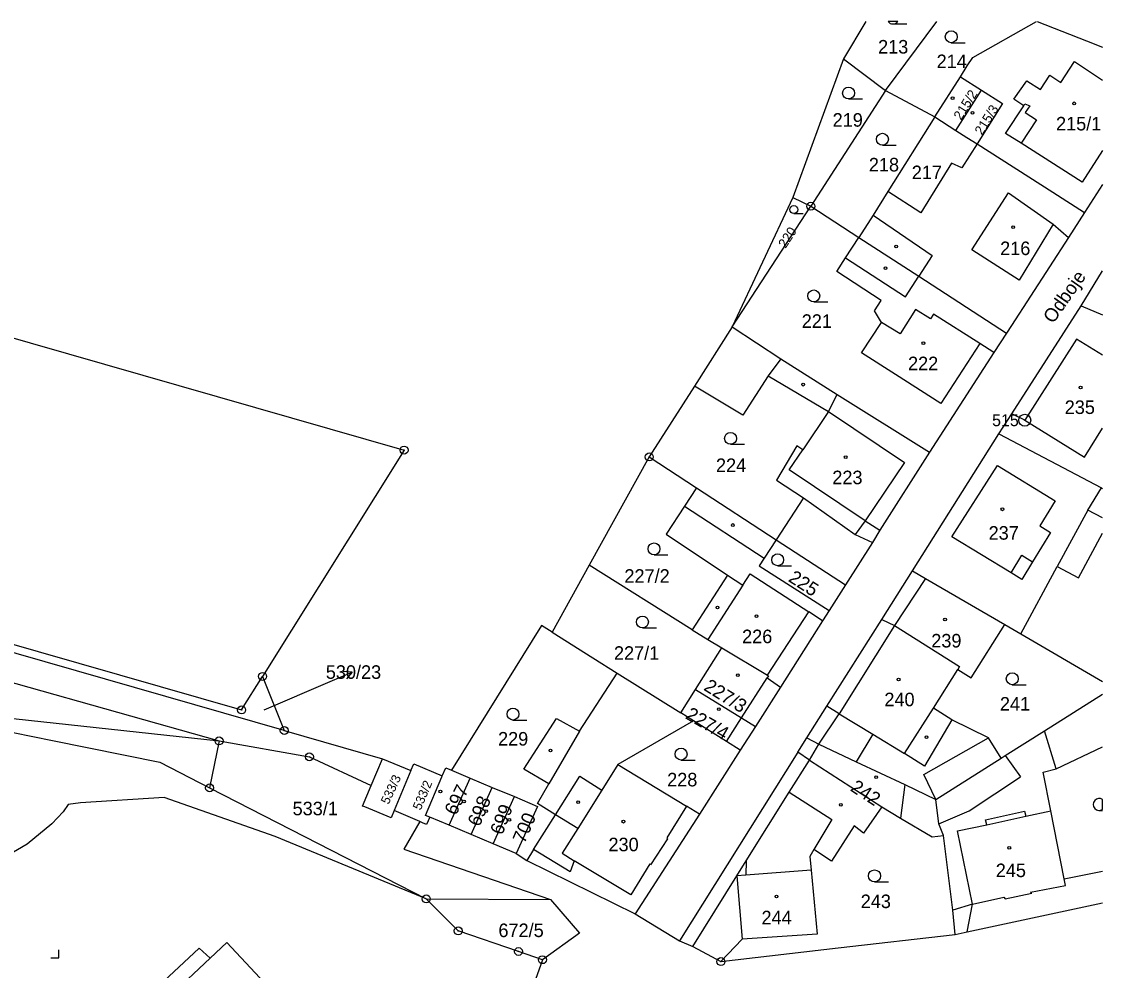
# Model space of a CAD drawing. Extents: x -749778 to -749372, y -967291 to -966955.
# Drawn here: x -749507.7 to -749371.9, y -967074.2 to -966955.1 of the extents above; entities that cross this region are included whole.
import ezdxf

# ---------------------------------------------------------------- set-up
doc = ezdxf.new("R2010")
doc.units = 0
for name, color, linetype in [('Hranice parcel', 7, 'Continuous'), ('Parcelní čísla', 7, 'Continuous'), ('Pop  PČ popisy', 7, 'Continuous'), ('Vnitřní kresba', 7, 'Continuous'), ('Značky bodu BP', 7, 'Continuous'), ('Značky budov', 7, 'Continuous'), ('Značky kultur', 7, 'Continuous')]:
    doc.layers.add(name, color=color, linetype=linetype)

msp = doc.modelspace()

# ---------------------------------------------------------------- linework, layer by layer
at = {"layer": 'Hranice parcel'}
for p, q in [((-749401.64, -966955.06), (-749404.45, -966959.75)), ((-749399.15, -966963.7), (-749392.71, -966955.06)), ((-749404.45, -966959.75), (-749410.8, -966977.16)), ((-749404.45, -966959.75), (-749399.15, -966963.7)), ((-749392.98, -966967.04), (-749389.74, -966962)), ((-749389.74, -966962), (-749387.12, -966963.67)), ((-749399.15, -966963.7), (-749408.54, -966978.26)), ((-749399.15, -966963.7), (-749392.98, -966967.04)), ((-749390.32, -966968.74), (-749387.12, -966963.67)), ((-749392.98, -966967.04), (-749398.86, -966976.41)), ((-749392.98, -966967.04), (-749390.32, -966968.74)), ((-749410.8, -966977.16), (-749418.41, -966993.42)), ((-749418.41, -966993.42), (-749408.54, -966978.26)), ((-749410.8, -966977.16), (-749408.54, -966978.26)), ((-749408.54, -966978.26), (-749402.52, -966982.17)), ((-749374.61, -966990.75), (-749371.93, -966986.38)), ((-749383.32, -967004.33), (-749374.61, -966990.75)), ((-749374.61, -966990.75), (-749371.93, -966991.91)), ((-749418.41, -966993.42), (-749412.33, -966997.43)), ((-749383.99, -966994.19), (-749385.55, -966996.62)), ((-749385.55, -966996.62), (-749393.64, -967009.16)), ((-749384.94, -967006.84), (-749383.32, -967004.33)), ((-749395.76, -967024.07), (-749384.94, -967006.84)), ((-749384.94, -967006.84), (-749372.05, -967013.63)), ((-749428.84, -967009.74), (-749436.39, -967023.36)), ((-749428.84, -967009.74), (-749422.9, -967013.62)), ((-749422.9, -967013.62), (-749412.9, -967020.16)), ((-749372.05, -967013.63), (-749371.93, -967013.7)), ((-749412.9, -967020.16), (-749404.2, -967025.83)), ((-749400.81, -967020.48), (-749404.2, -967025.83)), ((-749436.39, -967023.36), (-749441.05, -967031.75)), ((-749423.46, -967031.47), (-749436.39, -967023.36)), ((-749399.64, -967030.16), (-749395.76, -967024.07)), ((-749404.2, -967025.83), (-749406.26, -967029.05)), ((-749384.17, -967030.81), (-749382.16, -967031.98)), ((-749382.16, -967031.98), (-749371.93, -967037.94)), ((-749423.02, -967038.95), (-749419.71, -967033.73)), ((-749477.4, -967037.32), (-749474.68, -967044.11)), ((-749432.85, -967036.91), (-749424.89, -967041.9)), ((-749424.89, -967041.9), (-749423.02, -967038.95)), ((-749412.36, -967038.68), (-749415.5, -967043.61)), ((-749379.22, -967044.17), (-749371.93, -967039.55)), ((-749423.3, -967042.9), (-749424.89, -967041.9)), ((-749415.5, -967043.61), (-749417.42, -967046.59)), ((-749474.68, -967044.11), (-749462.35, -967047.65)), ((-749482.86, -967045.42), (-749484.05, -967051.31)), ((-749463.76, -967051), (-749462.35, -967047.65)), ((-749462.35, -967047.65), (-749458.78, -967049.15)), ((-749392.83, -967052.77), (-749384.63, -967047.59)), ((-749408.72, -967047.82), (-749399.61, -967053.68)), ((-749458.78, -967049.15), (-749460.89, -967054.16)), ((-749453.97, -967056.02), (-749451.31, -967050.08)), ((-749453.69, -967049.08), (-749451.31, -967050.08)), ((-749451.31, -967050.08), (-749448.55, -967051.25)), ((-749484.05, -967051.31), (-749456.84, -967065.27)), ((-749451.21, -967057.18), (-749448.55, -967051.25)), ((-749448.55, -967051.25), (-749445.78, -967052.41)), ((-749448.44, -967058.35), (-749445.78, -967052.41)), ((-749453.97, -967056.02), (-749456.38, -967054.98)), ((-749451.21, -967057.18), (-749453.97, -967056.02)), ((-749448.44, -967058.35), (-749451.21, -967057.18)), ((-749445.54, -967059.58), (-749448.44, -967058.35)), ((-749445.54, -967059.58), (-749444.23, -967060.44)), ((-749443.36, -967059.06), (-749444.23, -967060.44)), ((-749456.84, -967065.27), (-749441.22, -967065.32)), ((-749388.93, -967069.4), (-749371.93, -967065.77)), ((-749390.43, -967069.72), (-749388.93, -967069.4)), ((-749423.38, -967071.23), (-749419.84, -967073.14))]:
    msp.add_line(p, q, dxfattribs=at)
for points in [[(-749571.65, -966955.06), (-749539.45, -966985.97), (-749459.63, -967008.89), (-749477.4, -967037.32)], [(-749389.74, -966962), (-749388.9, -966960.6), (-749388.18, -966959.58), (-749380.2, -966955.06)], [(-749380.11, -966955.06), (-749373.91, -966957.49), (-749371.93, -966958.26)], [(-749387.12, -966963.67), (-749384.49, -966965.34), (-749387.66, -966970.43)], [(-749390.32, -966968.74), (-749388.97, -966969.6), (-749387.66, -966970.43)], [(-749387.66, -966970.43), (-749389.57, -966973.44), (-749390.89, -966972.83), (-749394.71, -966979.08), (-749398.86, -966976.41)], [(-749387.66, -966970.43), (-749378.15, -966976.5), (-749374.17, -966979.03)], [(-749371.93, -966975.52), (-749374.17, -966979.03)], [(-749398.86, -966976.41), (-749400.72, -966979.37), (-749402.52, -966982.17)], [(-749374.17, -966979.03), (-749376.2, -966982.16), (-749383.36, -966993.23), (-749383.99, -966994.19)], [(-749385.55, -966996.62), (-749387.32, -966995.49), (-749392.2, -967003.05), (-749397.91, -966999.38), (-749402.2, -966996.68), (-749399.65, -966992.84), (-749400.54, -966991.38), (-749399.7, -966990.1), (-749405.3, -966986.46), (-749404.19, -966984.74), (-749402.52, -966982.17)], [(-749402.52, -966982.17), (-749395, -966987.05), (-749383.99, -966994.19)], [(-749418.41, -966993.42), (-749423.15, -967000.85), (-749428.84, -967009.74)], [(-749371.93, -966996.95), (-749375.17, -966994.97), (-749381.68, -967005.13), (-749383.32, -967004.33)], [(-749412.33, -966997.43), (-749413.92, -966999.57), (-749406.32, -967004.03), (-749409.55, -967008.84), (-749410.29, -967008.34), (-749412.86, -967012.66), (-749409.45, -967014.88), (-749402.96, -967019.48), (-749400.81, -967020.48)], [(-749412.33, -966997.43), (-749405.24, -967001.89), (-749393.64, -967009.16)], [(-749573, -967005.05), (-749572.31, -967004.33), (-749556.39, -967019.6), (-749480.03, -967041.53), (-749477.4, -967037.32)], [(-749474.68, -967044.11), (-749556.9, -967020.49), (-749573, -967005.05)], [(-749393.64, -967009.16), (-749399.9, -967018.94), (-749400.81, -967020.48)], [(-749422.9, -967013.62), (-749424.41, -967015.93), (-749426.7, -967019.44), (-749419, -967024.61), (-749423.46, -967031.47)], [(-749371.93, -967017.41), (-749373.77, -967016.42), (-749372.05, -967013.63)], [(-749412.9, -967020.16), (-749414.4, -967022.46), (-749415.04, -967023.44), (-749406.26, -967029.05)], [(-749382.16, -967031.98), (-749377.59, -967023.5), (-749374.95, -967024.93), (-749371.93, -967019.32)], [(-749562.74, -967024.63), (-749560.29, -967023.62), (-749554.11, -967025.29), (-749533.97, -967031.01), (-749482.86, -967045.42)], [(-749395.76, -967024.07), (-749394.16, -967025), (-749384.17, -967030.81)], [(-749562.74, -967024.63), (-749554.44, -967027.88), (-749535.11, -967032.59), (-749510.28, -967042.45), (-749482.86, -967045.42)], [(-749406.26, -967029.05), (-749407.06, -967030.32), (-749412.36, -967038.68)], [(-749441.05, -967031.75), (-749442.35, -967030.94), (-749453.69, -967049.08)], [(-749409.05, -967045.02), (-749406.55, -967041.06), (-749399.64, -967030.16)], [(-749399.64, -967030.16), (-749398.05, -967030.92), (-749389.87, -967036.09), (-749390.09, -967036.44)], [(-749390.09, -967036.44), (-749388.43, -967037.5), (-749384.17, -967030.81)], [(-749441.05, -967031.75), (-749435.93, -967034.97), (-749432.85, -967036.91)], [(-749423.46, -967031.47), (-749421.49, -967032.66), (-749419.71, -967033.73)], [(-749419.71, -967033.73), (-749414, -967037.17), (-749413.88, -967037.25), (-749414.03, -967037.48), (-749412.36, -967038.68)], [(-749384.63, -967047.59), (-749386.24, -967045.05), (-749390.84, -967042.77), (-749393.16, -967041.3), (-749390.09, -967036.44)], [(-749443.36, -967059.06), (-749440.62, -967054.69), (-749442.87, -967053.3), (-749441.47, -967050.81), (-749444.59, -967048.98), (-749440.47, -967042.62), (-749437.59, -967044.18), (-749432.85, -967036.91)], [(-749423.02, -967038.95), (-749417.25, -967042.52), (-749415.5, -967043.61)], [(-749423.3, -967042.9), (-749432.78, -967048.4), (-749424.15, -967053.6)], [(-749417.42, -967046.59), (-749419.15, -967045.5), (-749423.3, -967042.9)], [(-749511.23, -967043.86), (-749503.78, -967045.37), (-749490.3, -967048.1), (-749484.05, -967051.31)], [(-749388.93, -967069.4), (-749388.25, -967065.91), (-749384.3, -967065.05), (-749384.16, -967065.25), (-749380.81, -967064.55), (-749380.94, -967064.41), (-749376.58, -967063.57), (-749376.74, -967062.74), (-749378.4, -967054.22), (-749379.35, -967049.36), (-749377.75, -967048.93), (-749379.22, -967044.17)], [(-749384.63, -967047.59), (-749384.13, -967047.27), (-749379.22, -967044.17)], [(-749482.86, -967045.42), (-749471.52, -967047.42), (-749463.76, -967051)], [(-749408.72, -967047.82), (-749410.19, -967046.82), (-749409.05, -967045.02)], [(-749409.05, -967045.02), (-749407.55, -967045.82), (-749402.87, -967048.03), (-749396.76, -967050.9), (-749392.83, -967052.77)], [(-749417.42, -967046.59), (-749422.52, -967054.6), (-749424.15, -967053.6)], [(-749458.78, -967049.15), (-749458.42, -967048.3), (-749454.83, -967049.79)], [(-749454.83, -967049.79), (-749454.4, -967048.78), (-749453.69, -967049.08)], [(-749423.38, -967071.23), (-749417.84, -967062.35), (-749416.68, -967060.49), (-749411.25, -967051.85), (-749408.72, -967047.82)], [(-749456.38, -967054.98), (-749456.93, -967054.77), (-749454.88, -967049.92), (-749454.83, -967049.79)], [(-749460.89, -967054.16), (-749461.27, -967055.08), (-749464.54, -967053.71), (-749464.85, -967053.6), (-749463.76, -967051)], [(-749456.84, -967065.27), (-749475.82, -967057.43), (-749489.74, -967052.51), (-749500.28, -967053.21), (-749501.83, -967053.4), (-749502.46, -967054.34), (-749503.87, -967055.82), (-749506.95, -967058.39), (-749517.45, -967064.49), (-749518.23, -967065.16), (-749527.61, -967079.16), (-749530.11, -967082.89), (-749535.6, -967090.98), (-749536.66, -967092.72), (-749536.81, -967092.95)], [(-749445.78, -967052.41), (-749442.88, -967053.64), (-749445.54, -967059.58)], [(-749391.88, -967057.32), (-749392.46, -967055.85), (-749392.83, -967052.77)], [(-749457.65, -967055.55), (-749460.27, -967054.43), (-749460.89, -967054.16)], [(-749424.15, -967053.6), (-749426.65, -967057.58), (-749426.55, -967057.72), (-749428.68, -967060.98), (-749428.76, -967060.87), (-749431.16, -967064.77), (-749438.27, -967060.5), (-749438.76, -967061.88), (-749443.36, -967059.06)], [(-749399.61, -967053.68), (-749401.92, -967057), (-749403.09, -967056.09), (-749405.93, -967060.54), (-749408.17, -967059.07), (-749408.69, -967059.92), (-749408.52, -967061.65), (-749407.75, -967069.68), (-749417.19, -967070.34), (-749419.84, -967073.14)], [(-749399.61, -967053.68), (-749397.29, -967055.14), (-749393.3, -967057.46), (-749391.88, -967057.32)], [(-749457.65, -967055.55), (-749459.64, -967059.03), (-749441.22, -967065.32)], [(-749456.38, -967054.98), (-749456.81, -967055.91), (-749457.32, -967055.69), (-749457.65, -967055.55)], [(-749390.43, -967069.72), (-749390.72, -967066.68), (-749391.88, -967057.32)], [(-749444.23, -967060.44), (-749430.62, -967067.16), (-749425.05, -967070.52), (-749423.38, -967071.23)], [(-749442.25, -967072.9), (-749445.26, -967071.87), (-749452.83, -967069.28), (-749456.84, -967065.27)], [(-749441.22, -967065.32), (-749437.58, -967069.58), (-749442.25, -967072.9)], [(-749481.87, -967070.74), (-749475.36, -967077.73), (-749479.93, -967081.99), (-749476.5, -967086), (-749476.25, -967085.49), (-749469.41, -967092.9), (-749474.44, -967097.68), (-749477.63, -967094.09), (-749480.99, -967090.3), (-749480.38, -967089.72), (-749483.9, -967085.69), (-749493.15, -967094.3), (-749499.66, -967087.31), (-749497.42, -967085.23), (-749498.64, -967083.86), (-749485.37, -967071.47), (-749483.98, -967072.71), (-749481.87, -967070.74)], [(-749419.84, -967073.14), (-749405.1, -967071.4), (-749390.43, -967069.72)], [(-749442.25, -967072.9), (-749444.69, -967079.75), (-749466.53, -967099.64), (-749491.04, -967118.52)]]:
    msp.add_lwpolyline(points, dxfattribs=at)
at = {"layer": 'Pop  PČ popisy'}
for p, q in [((-749468.92, -967037.95), (-749466.16, -967036.78)), ((-749466.16, -967036.78), (-749467.28, -967036.71)), ((-749466.16, -967036.78), (-749466.88, -967037.63)), ((-749477.22, -967041.5), (-749468.92, -967037.95))]:
    msp.add_line(p, q, dxfattribs=at)
at = {"layer": 'Vnitřní kresba'}
for p, q in [((-749377.14, -966962.71), (-749375.42, -966960.09)), ((-749375.42, -966960.09), (-749371.93, -966962.4)), ((-749379.72, -966963.58), (-749378.55, -966961.78)), ((-749378.55, -966961.78), (-749377.14, -966962.71)), ((-749383.05, -966964.82), (-749381.4, -966962.49)), ((-749381.4, -966962.49), (-749379.72, -966963.58)), ((-749381.81, -966965.63), (-749383.05, -966964.82)), ((-749384.08, -966969.1), (-749381.81, -966965.63)), ((-749381.81, -966965.63), (-749381.65, -966965.39)), ((-749381.65, -966965.39), (-749381.05, -966965.63)), ((-749381.05, -966965.63), (-749381.61, -966966.47)), ((-749380.21, -966967.39), (-749382.15, -966970.33)), ((-749381.61, -966966.47), (-749380.21, -966967.39)), ((-749382.15, -966970.33), (-749384.08, -966969.1)), ((-749374.46, -966975.23), (-749382.15, -966970.33)), ((-749371.93, -966971.24), (-749374.46, -966975.23)), ((-749388.34, -966983.73), (-749383.73, -966976.55)), ((-749383.73, -966976.55), (-749378.1, -966980.52)), ((-749400.72, -966979.37), (-749393.31, -966984.45)), ((-749378.1, -966980.52), (-749382.4, -966987.54)), ((-749378.1, -966980.52), (-749376.2, -966982.16)), ((-749382.4, -966987.54), (-749388.34, -966983.73)), ((-749404.19, -966984.74), (-749396.67, -966989.63)), ((-749393.31, -966984.45), (-749395, -966987.05)), ((-749396.67, -966989.63), (-749395, -966987.05)), ((-749395.39, -966991.23), (-749397.32, -966994.3)), ((-749393.53, -966992.41), (-749395.39, -966991.23)), ((-749393.15, -966991.82), (-749393.53, -966992.41)), ((-749387.32, -966995.49), (-749393.15, -966991.82)), ((-749397.32, -966994.3), (-749399.65, -966992.84)), ((-749413.92, -966999.57), (-749417.1, -967004.5)), ((-749417.1, -967004.5), (-749423.15, -967000.85)), ((-749406.32, -967004.03), (-749405.24, -967001.89)), ((-749406.32, -967004.03), (-749396.79, -967010.44)), ((-749381.68, -967005.13), (-749374.16, -967009.78)), ((-749374.16, -967009.78), (-749371.93, -967006.13)), ((-749411.26, -967011.37), (-749409.55, -967008.84)), ((-749396.79, -967010.44), (-749401.72, -967017.78)), ((-749390.84, -967019.79), (-749385.11, -967010.82)), ((-749385.11, -967010.82), (-749377.88, -967015.27)), ((-749401.72, -967017.78), (-749411.26, -967011.37)), ((-749409.45, -967014.88), (-749412.9, -967020.16)), ((-749424.41, -967015.93), (-749414.4, -967022.46)), ((-749377.88, -967015.27), (-749379.8, -967018.41)), ((-749373.77, -967016.42), (-749377.59, -967023.5)), ((-749401.72, -967017.78), (-749402.96, -967019.48)), ((-749401.72, -967017.78), (-749399.9, -967018.94)), ((-749379.8, -967018.41), (-749378.45, -967019.23)), ((-749383.4, -967024.32), (-749390.84, -967019.79)), ((-749378.45, -967019.23), (-749380.7, -967022.93)), ((-749383.4, -967024.32), (-749382.05, -967022.1)), ((-749380.7, -967022.93), (-749382.06, -967025.14)), ((-749382.05, -967022.1), (-749380.7, -967022.93)), ((-749419, -967024.61), (-749417.07, -967025.86)), ((-749417.07, -967025.86), (-749416.15, -967024.43)), ((-749416.15, -967024.43), (-749408.8, -967029.2)), ((-749382.06, -967025.14), (-749383.4, -967024.32)), ((-749417.07, -967025.86), (-749421.49, -967032.66)), ((-749394.16, -967025), (-749398.05, -967030.92)), ((-749414, -967037.17), (-749408.8, -967029.2)), ((-749407.06, -967030.32), (-749408.8, -967029.2)), ((-749398.05, -967030.92), (-749404.99, -967042)), ((-749417.25, -967042.52), (-749414.03, -967037.48)), ((-749407.55, -967045.82), (-749404.99, -967042)), ((-749404.99, -967042), (-749406.55, -967041.06)), ((-749404.99, -967042), (-749400.75, -967044.59)), ((-749396.78, -967047.02), (-749393.16, -967041.3)), ((-749419.15, -967045.5), (-749417.25, -967042.52)), ((-749390.84, -967042.77), (-749394.29, -967048.59)), ((-749437.59, -967044.18), (-749441.47, -967050.81)), ((-749400.75, -967044.59), (-749402.87, -967048.03)), ((-749400.75, -967044.59), (-749396.78, -967047.02)), ((-749408.72, -967047.82), (-749407.55, -967045.82)), ((-749394.37, -967049.62), (-749386.24, -967045.05)), ((-749377.75, -967048.93), (-749371.93, -967046.17)), ((-749410.19, -967046.82), (-749425.05, -967070.52)), ((-749394.29, -967048.59), (-749396.78, -967047.02)), ((-749384.13, -967047.27), (-749382.21, -967049.91)), ((-749432.78, -967048.4), (-749434.78, -967051.59)), ((-749440.62, -967054.69), (-749437.57, -967049.83)), ((-749437.57, -967049.83), (-749434.78, -967051.59)), ((-749392.83, -967052.77), (-749394.37, -967049.62)), ((-749388.67, -967054.22), (-749382.21, -967049.91)), ((-749434.78, -967051.59), (-749437.82, -967056.42)), ((-749396.76, -967050.9), (-749397.29, -967055.14)), ((-749411.25, -967051.85), (-749405.89, -967055.31)), ((-749392.46, -967055.85), (-749388.67, -967054.22)), ((-749386.63, -967055.35), (-749381.72, -967054.25)), ((-749381.72, -967054.25), (-749381.55, -967054.89)), ((-749381.55, -967054.89), (-749378.4, -967054.22)), ((-749437.82, -967056.42), (-749440.62, -967054.69)), ((-749422.52, -967054.6), (-749430.62, -967067.16)), ((-749405.89, -967055.31), (-749408.17, -967059.07)), ((-749386.46, -967055.94), (-749386.63, -967055.35)), ((-749386.46, -967055.94), (-749381.55, -967054.89)), ((-749437.82, -967056.42), (-749439.77, -967059.52)), ((-749390.13, -967056.73), (-749386.46, -967055.94)), ((-749388.25, -967065.91), (-749390.13, -967056.73)), ((-749439.77, -967059.52), (-749438.27, -967060.5)), ((-749416.68, -967060.49), (-749416.69, -967062.27)), ((-749416.69, -967062.27), (-749417.84, -967062.35)), ((-749417.84, -967062.35), (-749417.19, -967070.34)), ((-749408.52, -967061.65), (-749416.69, -967062.27)), ((-749376.74, -967062.74), (-749371.93, -967061.8)), ((-749388.25, -967065.91), (-749390.72, -967066.68)), ((-749497.42, -967085.23), (-749483.98, -967072.71))]:
    msp.add_line(p, q, dxfattribs=at)
at = {"layer": 'Značky bodu BP'}
for centre, radius in [((-749408.54, -966978.26), 0.5), ((-749408.54, -966978.26), 0.0303), ((-749381.68, -967005.13), 0.75), ((-749381.68, -967005.13), 0.03), ((-749459.63, -967008.89), 0.5), ((-749459.63, -967008.89), 0.0303), ((-749428.84, -967009.74), 0.5), ((-749428.84, -967009.74), 0.0303), ((-749477.4, -967037.32), 0.5), ((-749477.4, -967037.32), 0.0303), ((-749480.03, -967041.53), 0.5), ((-749480.03, -967041.53), 0.0303), ((-749474.68, -967044.11), 0.5), ((-749482.86, -967045.42), 0.5), ((-749474.68, -967044.11), 0.0303), ((-749482.86, -967045.42), 0.0303), ((-749471.52, -967047.42), 0.5), ((-749471.52, -967047.42), 0.0303), ((-749484.05, -967051.31), 0.5), ((-749484.05, -967051.31), 0.0303), ((-749456.84, -967065.27), 0.5), ((-749456.84, -967065.27), 0.0303), ((-749452.83, -967069.28), 0.5), ((-749452.83, -967069.28), 0.0303), ((-749445.26, -967071.87), 0.5), ((-749445.26, -967071.87), 0.0303), ((-749442.25, -967072.9), 0.5), ((-749442.25, -967072.9), 0.0303), ((-749419.84, -967073.14), 0.5), ((-749419.84, -967073.14), 0.0303)]:
    msp.add_circle(centre, radius, dxfattribs=at)
at = {"layer": 'Značky budov'}
for centre in [(-749390.74, -966964.69), (-749375.48, -966965.33), (-749388.25, -966966.53), (-749383.14, -966980.89), (-749397.83, -966983.32), (-749399.18, -966986.04), (-749394.41, -966995.46), (-749409.5, -967000.66), (-749374.66, -967001.02), (-749404.17, -967009.78), (-749384.49, -967016.32), (-749418.33, -967018.3), (-749420.28, -967028.66), (-749415.36, -967029.76), (-749391.69, -967030.16), (-749417.72, -967037.17), (-749397.52, -967037.69), (-749420.11, -967041.44), (-749394.01, -967044.94), (-749441.25, -967046.63), (-749400.34, -967049.97), (-749455.07, -967051.76), (-749452.11, -967053.02), (-749437.77, -967053.1), (-749449.32, -967054.24), (-749404.77, -967053.46), (-749446.41, -967055.33), (-749432.09, -967055.56), (-749383.62, -967058.84), (-749412.85, -967064.97)]:
    msp.add_circle(centre, 0.175, dxfattribs=at)
at = {"layer": 'Značky kultur'}
for p, q in [((-749397.64, -966955.06), (-749398.84, -966955.06)), ((-749398.24, -966955.36), (-749396.49, -966955.36)), ((-749390.91, -966957.71), (-749389.16, -966957.71)), ((-749403.81, -966964.78), (-749402.06, -966964.78)), ((-749399.56, -966970.59), (-749397.81, -966970.59)), ((-749410.68, -966979.18), (-749409.5, -966979.18)), ((-749408.18, -966990.27), (-749406.43, -966990.27)), ((-749418.63, -967008.16), (-749416.88, -967008.16)), ((-749428.24, -967022.04), (-749426.49, -967022.04)), ((-749412.71, -967023.42), (-749410.96, -967023.42)), ((-749429.69, -967031.23), (-749427.94, -967031.23)), ((-749383.25, -967038.36), (-749381.5, -967038.36)), ((-749445.95, -967042.8), (-749444.2, -967042.8)), ((-749424.84, -967047.82), (-749423.09, -967047.82)), ((-749371.93, -967054.03), (-749371.93, -967052.77)), ((-749372.33, -967054.15), (-749371.93, -967054.15)), ((-749400.55, -967063.12), (-749398.8, -967063.12)), ((-749502.98, -967072.66), (-749502.98, -967071.66)), ((-749503.98, -967072.66), (-749502.98, -967072.66))]:
    msp.add_line(p, q, dxfattribs=at)
for centre, radius in [((-749390.91, -966956.96), 0.75), ((-749403.81, -966964.03), 0.75), ((-749399.56, -966969.84), 0.75), ((-749410.68, -966978.68), 0.502), ((-749408.18, -966989.52), 0.75), ((-749418.63, -967007.41), 0.75), ((-749428.24, -967021.29), 0.75), ((-749412.71, -967022.67), 0.75), ((-749429.69, -967030.48), 0.75), ((-749383.25, -967037.61), 0.75), ((-749445.95, -967042.05), 0.75), ((-749424.84, -967047.07), 0.75), ((-749400.55, -967062.37), 0.75)]:
    msp.add_circle(centre, radius, dxfattribs=at)
for centre, start, end in [((-749398.24, -966954.61), 216.8878, 323.1122), ((-749372.33, -967053.4), 57.5106, 302.4894)]:
    msp.add_arc(centre, 0.75, start, end, dxfattribs=at)

# ---------------------------------------------------------------- texts
at = {"layer": 'Parcelní čísla'}
for s, p in [('213', (-749400.1, -966959.07)), ('214', (-749392.75, -966960.9)), ('219', (-749405.81, -966968.26)), ('215/1', (-749377.75, -966968.73)), ('218', (-749401.26, -966973.88)), ('217', (-749395.87, -966974.85)), ('216', (-749384.77, -966984.39)), ('221', (-749409.69, -966993.53)), ('222', (-749396.34, -966998.85)), ('235', (-749376.66, -967004.35)), ('224', (-749420.46, -967011.64)), ('223', (-749405.85, -967013.17)), ('237', (-749386.22, -967020.14)), ('227/2', (-749431.96, -967025.55)), ('226', (-749417.18, -967033.14)), ('239', (-749393.42, -967033.68)), ('227/1', (-749433.27, -967035.23)), ('530/23', (-749469.46, -967037.62)), ('240', (-749399.31, -967041.06)), ('241', (-749384.8, -967041.61)), ('229', (-749447.83, -967046)), ('228', (-749426.59, -967051.13)), ('533/1', (-749473.63, -967054.76)), ('230', (-749433.96, -967059.28)), ('245', (-749385.32, -967062.53)), ('243', (-749402.28, -967066.42)), ('244', (-749414.74, -967068.46)), ('672/5', (-749447.78, -967070.06))]:
    msp.add_text(s, height=1.7, dxfattribs=at).set_placement(p)
for s, height, rotation, p in [('215/2', 1.2, 58, (-749389.69, -966967.52)), ('215/3', 1.2, 58, (-749387.04, -966969.41)), ('220', 1.2, 57, (-749411.72, -966983.61)), ('225', 1.7, 327, (-749411.48, -967025.29)), ('227/3', 1.7, 328, (-749422.11, -967038.96)), ('227/4', 1.7, 330, (-749424.41, -967042.54)), ('533/3', 1.139, 65, (-749461.58, -967053.47)), ('533/2', 1.139, 67, (-749457.55, -967054.2)), ('242', 1.7, 327, (-749403.7, -967051.6)), ('697', 1.7, 64, (-749453.12, -967054.88)), ('698', 1.7, 67, (-749450.16, -967056.29)), ('699', 1.7, 69, (-749447.3, -967057.34)), ('700', 1.7, 67, (-749444.5, -967058.4))]:
    msp.add_text(s, height=height, rotation=rotation, dxfattribs=at).set_placement(p)
at = {"layer": 'Pop  PČ popisy'}
msp.add_text('Odboje', height=1.7, rotation=55, dxfattribs=at).set_placement((-749378.11, -966993.09))
at = {"layer": 'Značky bodu BP'}
msp.add_text('515', height=1.5, dxfattribs=at).set_placement((-749385.78, -967005.88))

doc.saveas('drawing.dxf')
